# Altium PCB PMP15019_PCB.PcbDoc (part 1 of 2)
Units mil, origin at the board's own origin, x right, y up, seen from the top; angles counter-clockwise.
Board outline 3000 x 2000 mil, 6 copper layers (Top Layer, Signal Layer 1, Signal Layer 2, Signal Layer 3, Signal Layer 4, Bottom Layer), stack 61.6 mil thick; 82 components, 32 nets, 164 pads, 220 vias.
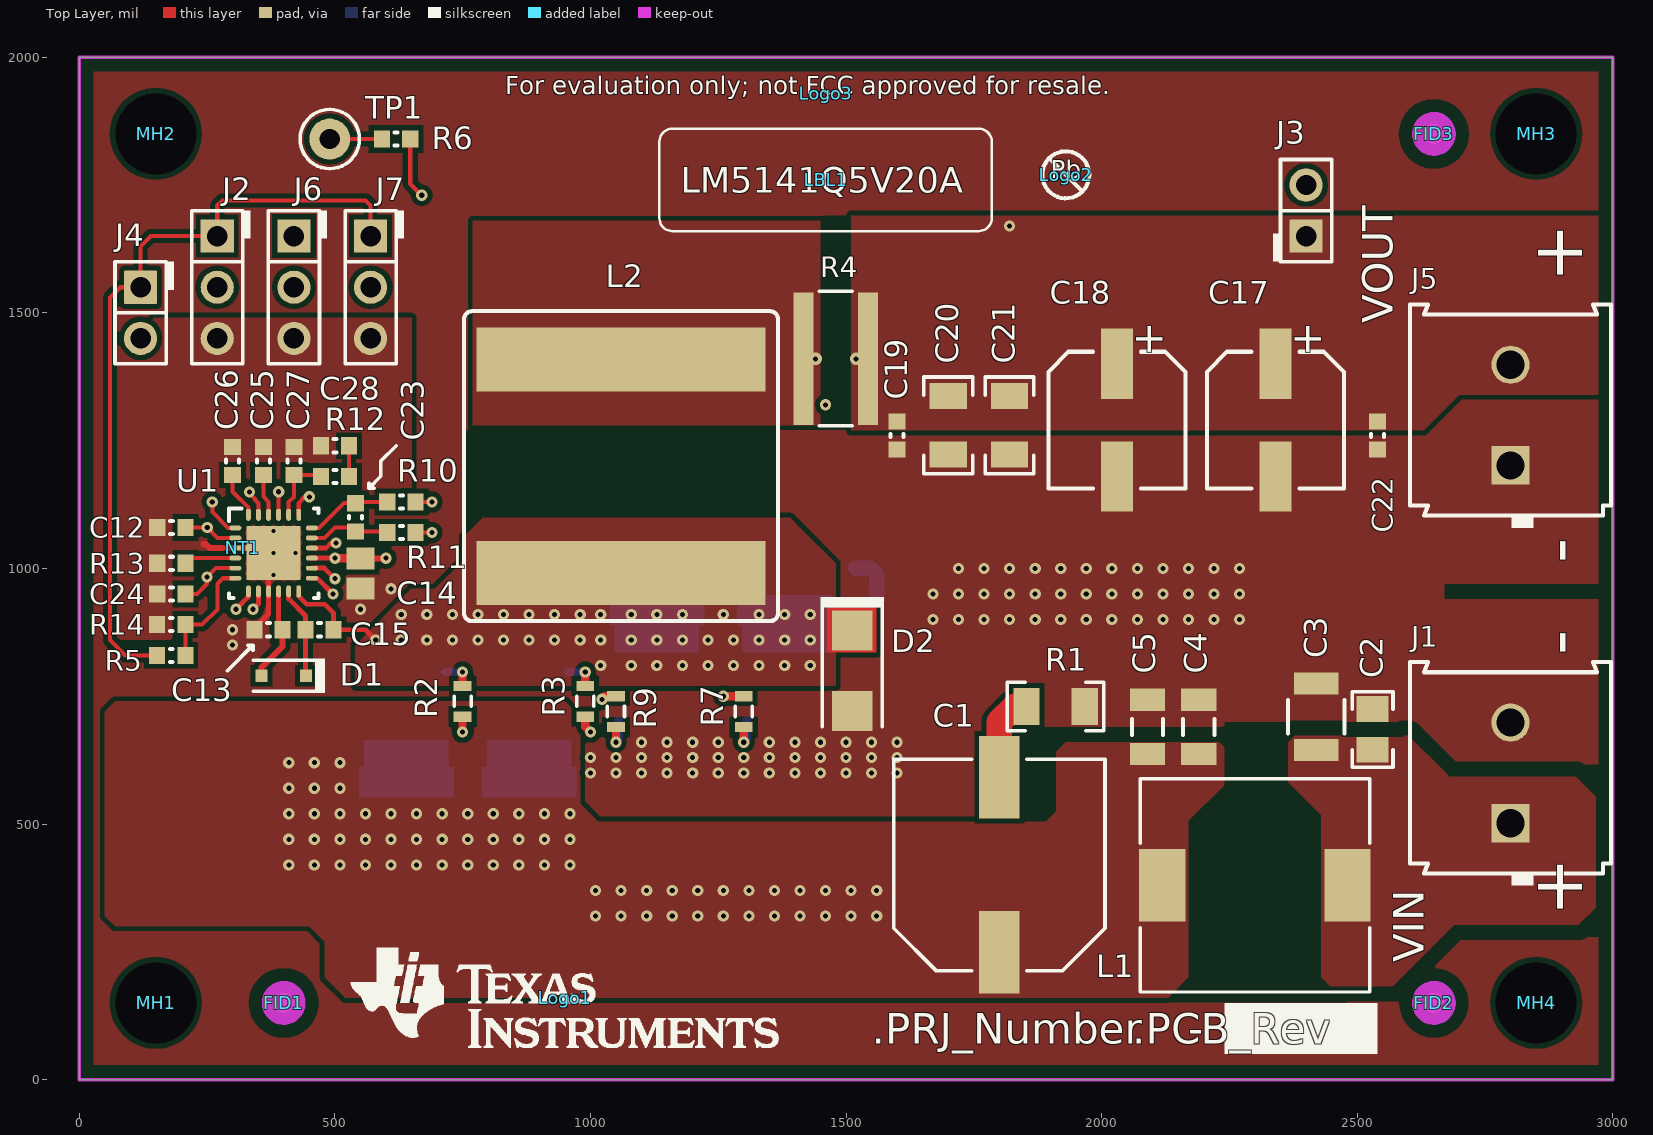
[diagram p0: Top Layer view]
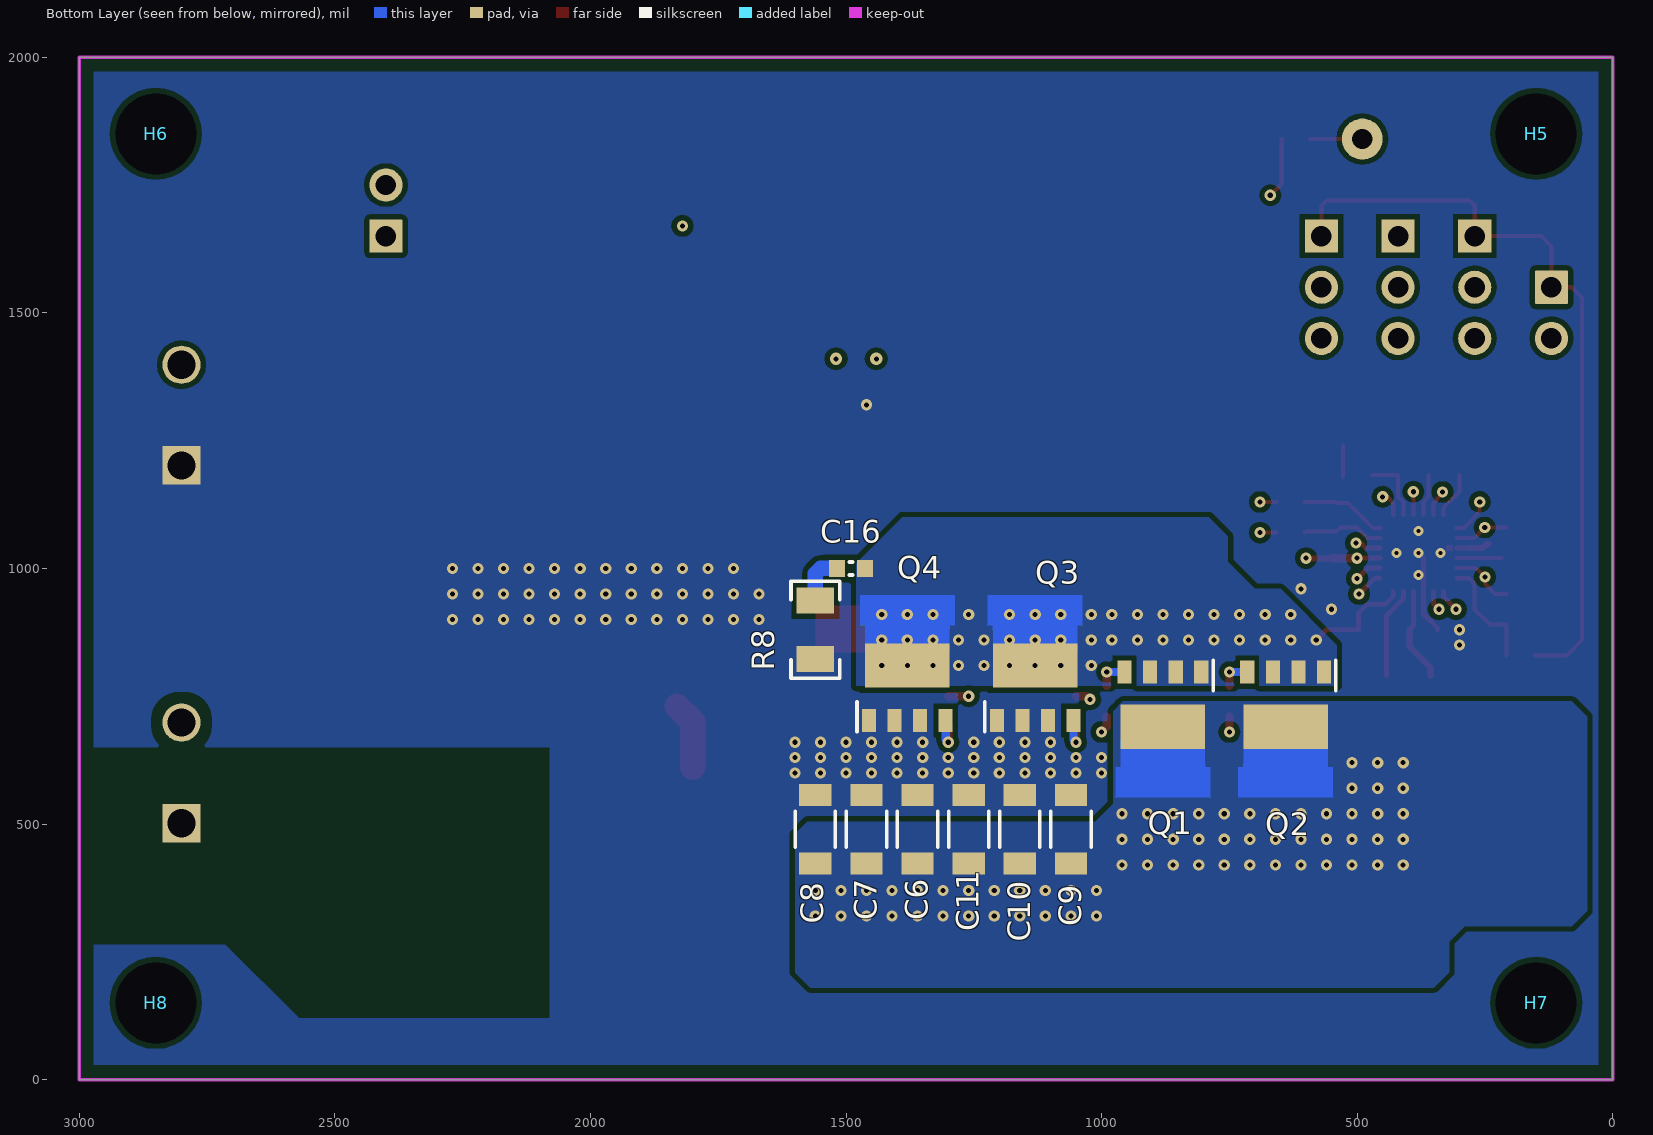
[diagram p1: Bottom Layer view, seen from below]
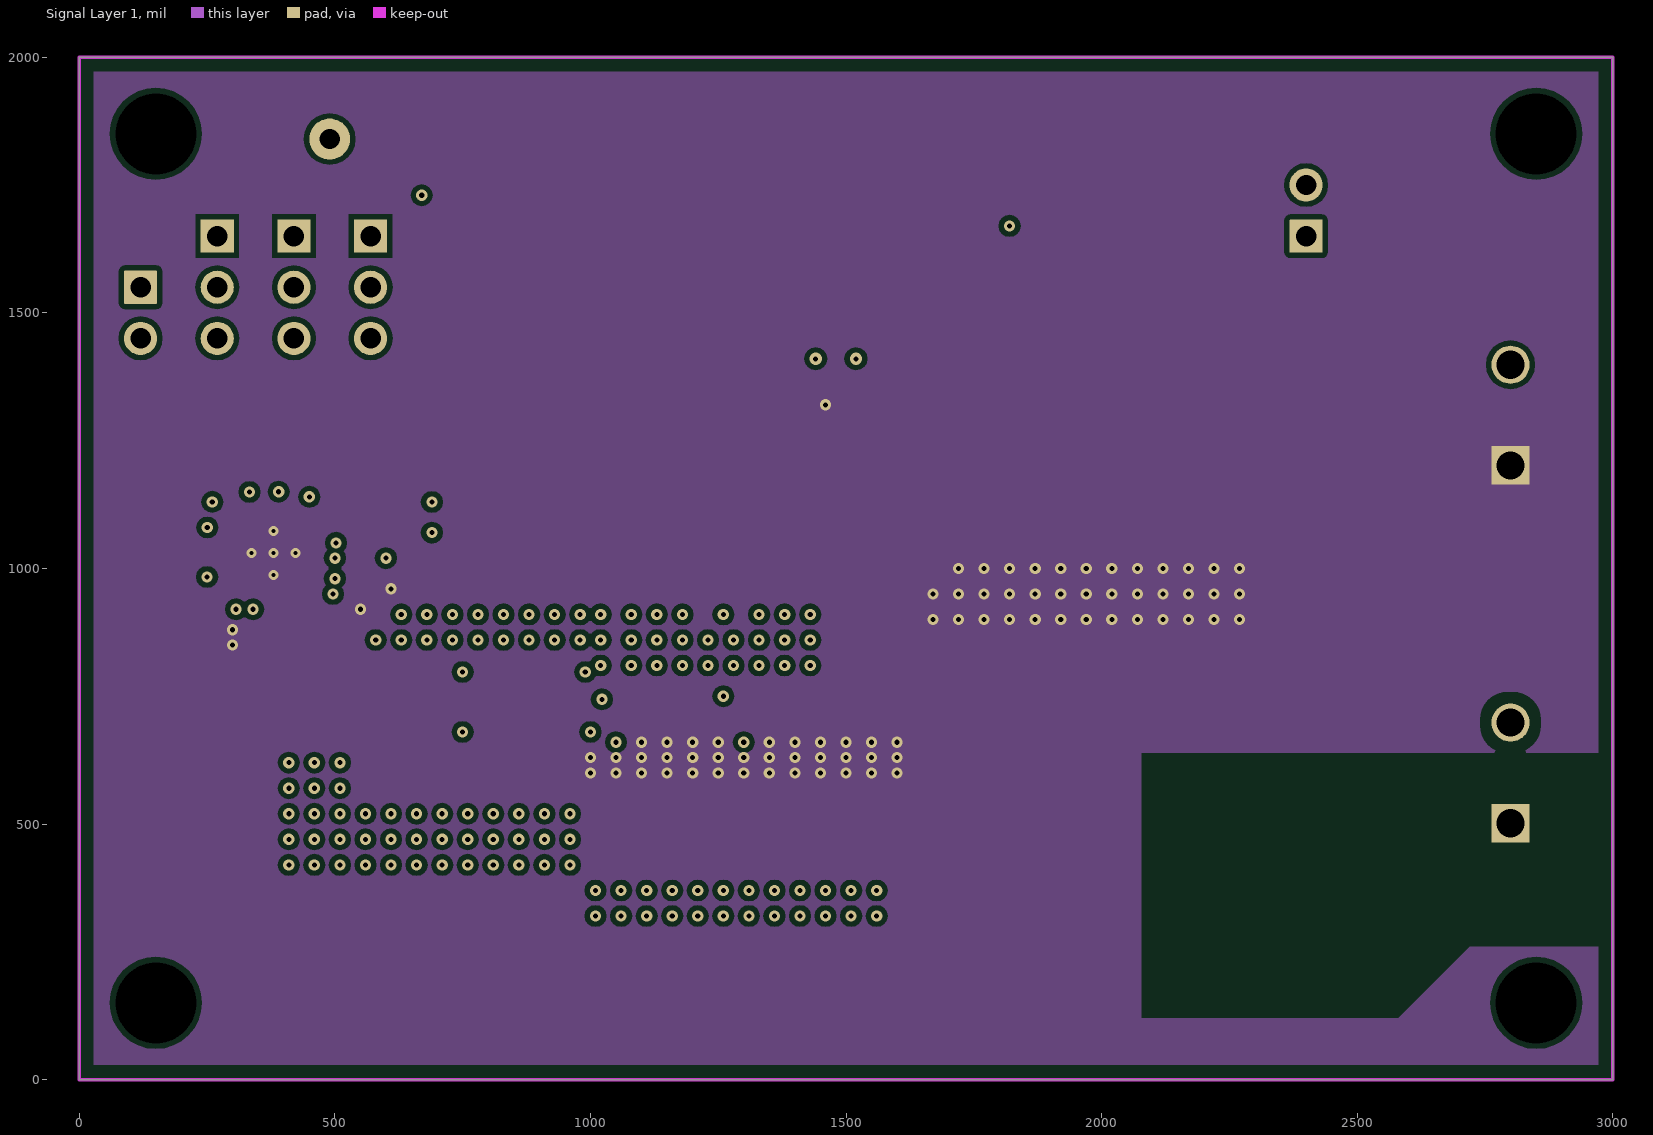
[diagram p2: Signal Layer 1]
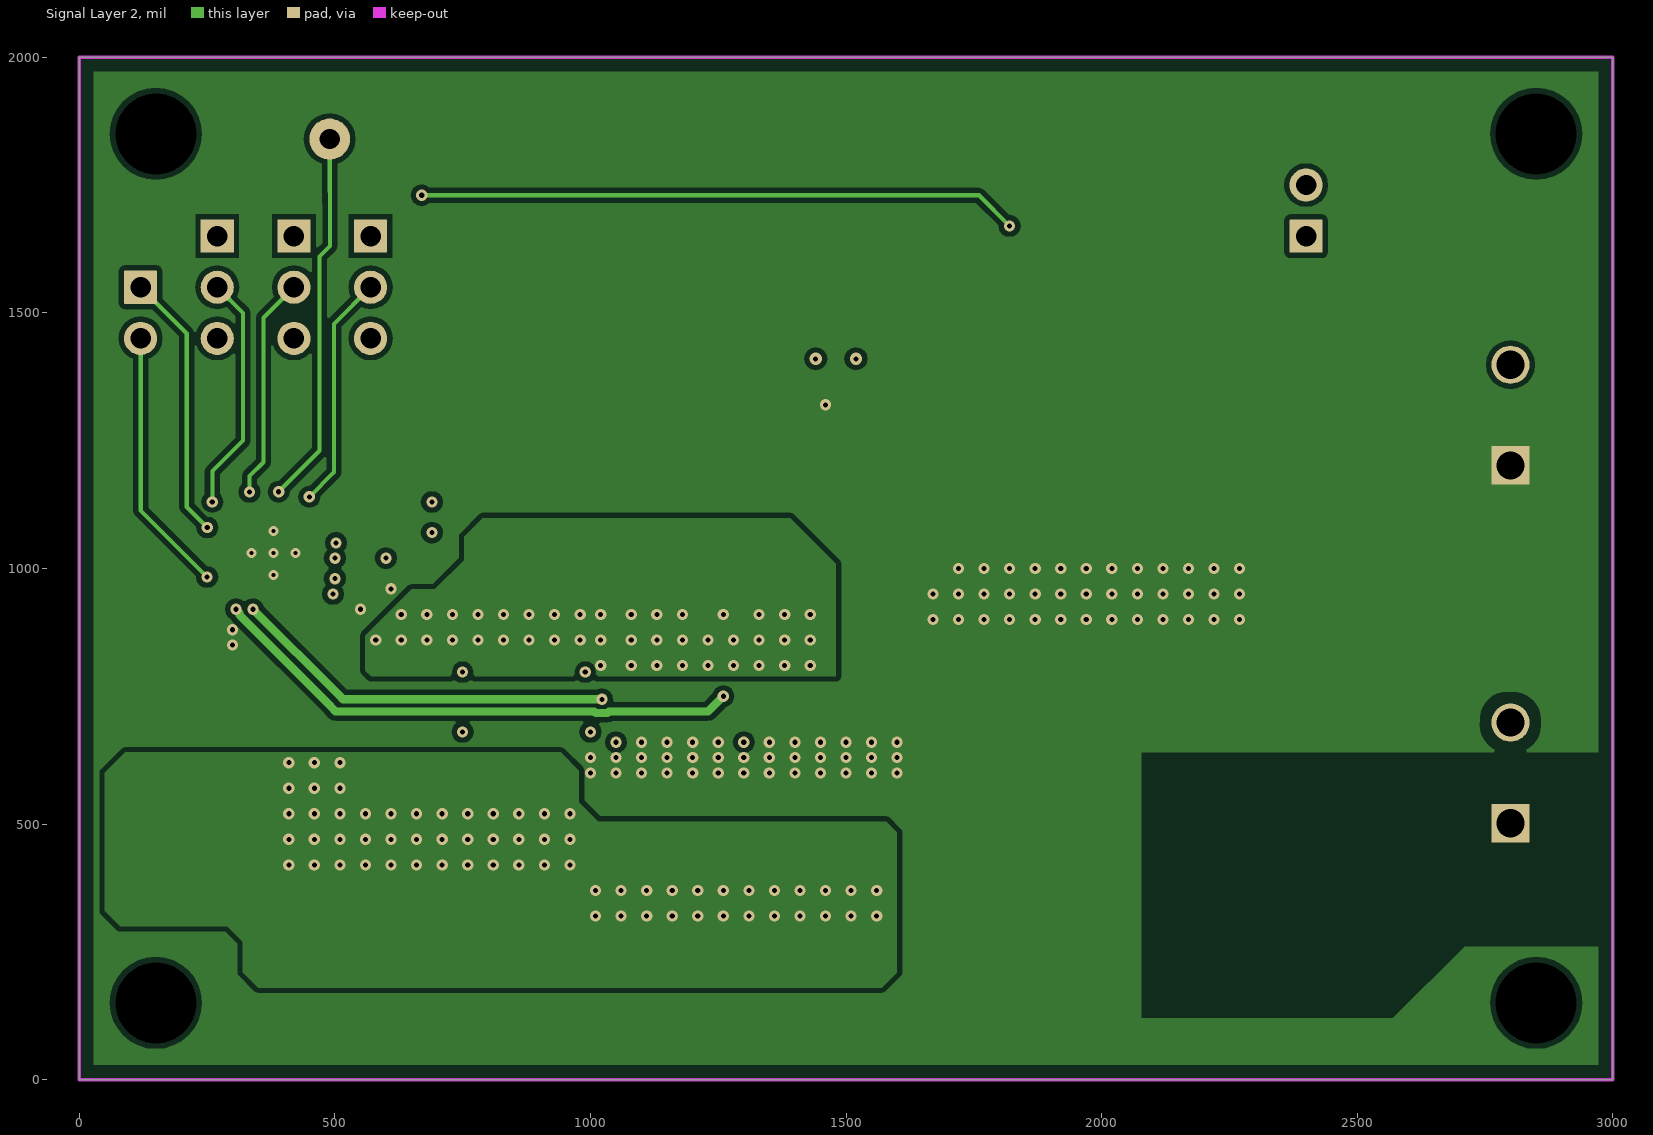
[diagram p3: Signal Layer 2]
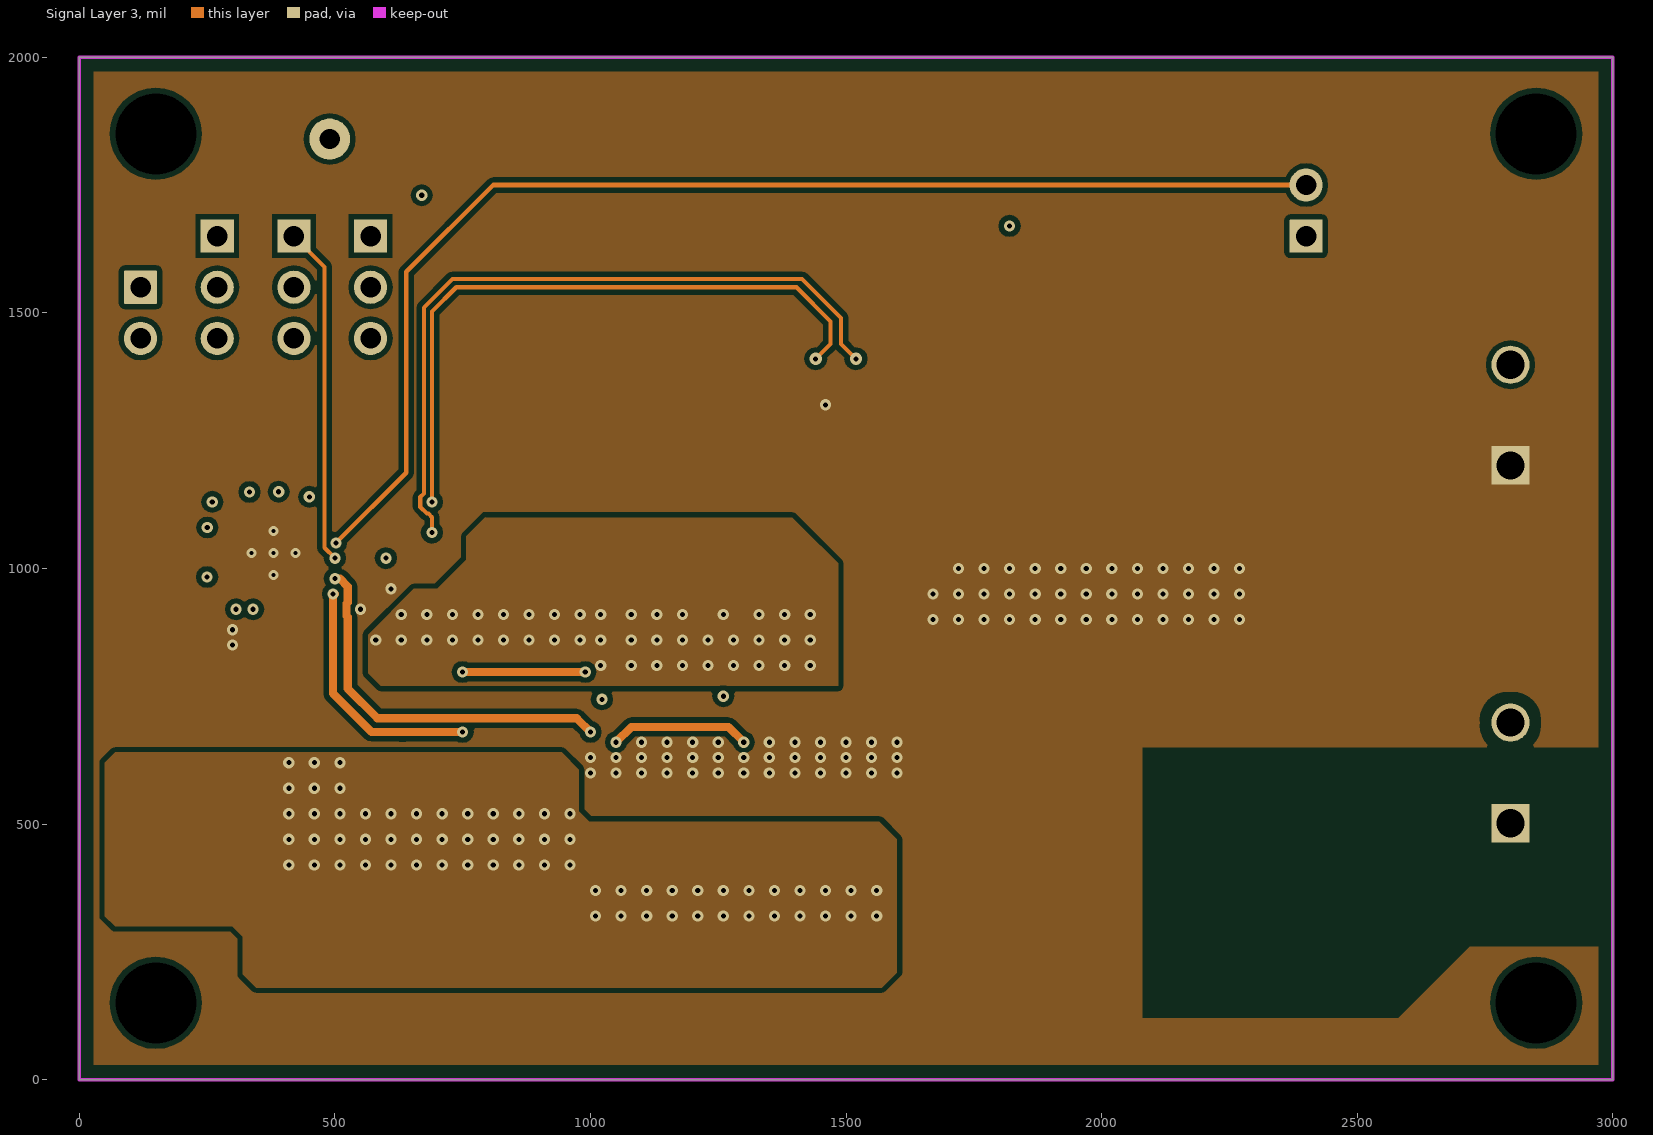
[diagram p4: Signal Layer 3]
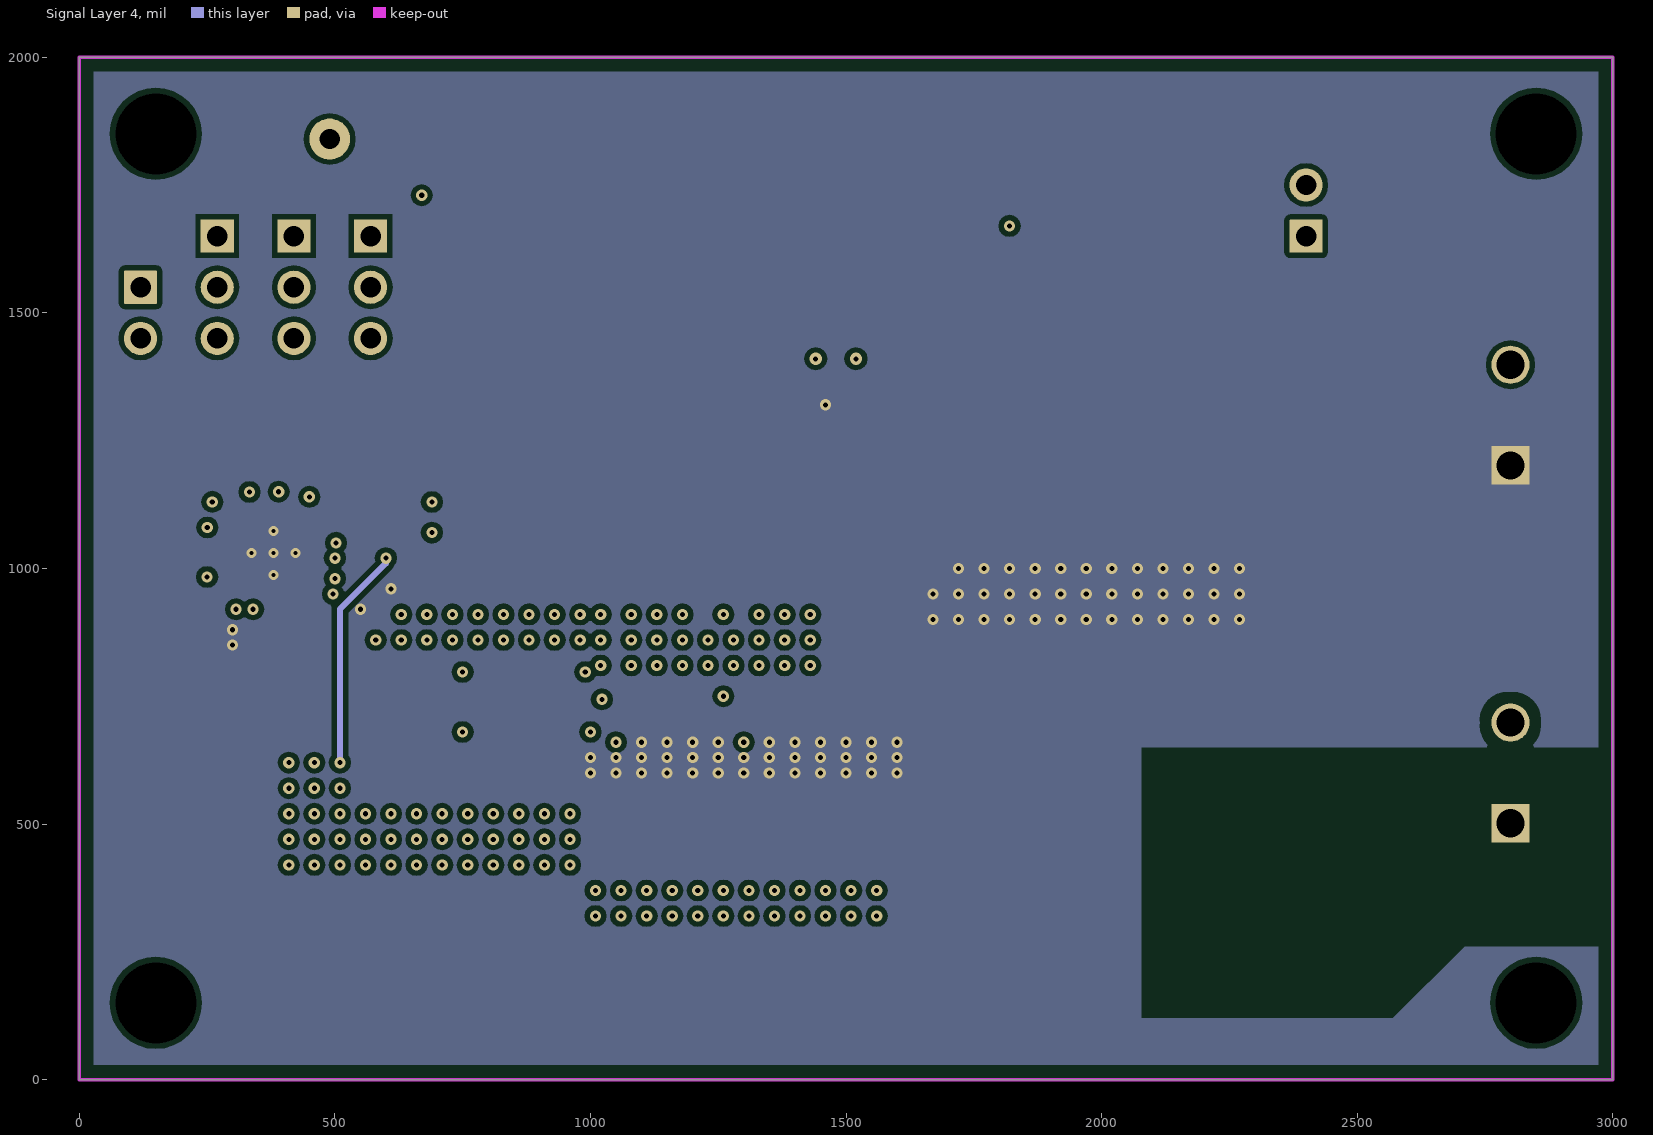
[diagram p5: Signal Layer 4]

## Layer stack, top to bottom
Top Solder: solder mask 0.4, Solder Resist, Dk 3.5
Top Layer: signal copper 4.2
Dielectric1: core 5, FR-4, Dk 4.8
Signal Layer 1: signal copper 2.8
Dielectric 3: prepreg 5, Dk 4.2
Signal Layer 2: signal copper 2.8
Dielectric 4: core 22, Dk 4.2
Signal Layer 3: signal copper 2.8
Dielectric 5: prepreg 5, Dk 4.2
Signal Layer 4: signal copper 2.8
Dielectric 2: core 5, Dk 4.2
Bottom Layer: signal copper 4.2
Bottom Solder: solder mask 0.4, Solder Resist, Dk 3.5

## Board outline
0,0 0,2000 3000,2000 3000,0

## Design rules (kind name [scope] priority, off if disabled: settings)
AcuteAngle [All] p1: minimum=4.50000000000000E+0001 checktracksonly=FALSE
AssemblyTestPointUsage [All] p1: valid=2
Clearance Clearance_Input [InNet('NetC2_1')] p1: gap=30
Clearance Clearance_Keepouts [((IsTrack Or IsArc) And Not InPoly) And IsFree and IsKeepOut vs ((IsTrack Or IsArc) And Not InPoly) And IsFree and IsKeepOut] p2: gap=0
Clearance Clearance_BoardEdge_MountingHoles [OnCopper and InComponentClass('Mounting Holes') vs IsKeepOut] p3: gap=40
Clearance Clearance_BoardEdge_Poly [OnCopper and InPoly vs IsKeepOut] p4: gap=25
Clearance Clearance_BoardEdge [OnCopper and Not InComponentClass('Logo') and not InComponentClass('FiducialMark') and not InRegion(1000,500,4000,800) and Not IsKeepout vs IsKeepOut] p5: gap=50
Clearance Clearance_Poly [InPolygon] p6: gap=10
Clearance [All] p7: gap=7.87
ComponentClearance ComponentClearance_NetTie [HasFootprint('RGE0024H') vs HasFootprint('Net-Tie_10mil')] p1: gap=0 collisioncheckmode=3 verticalgap=0 showdistances=FALSE
ComponentClearance ComponentClearance_MountingHoles_FiducialMarks [InComponentClass('Mounting Holes') vs InComponentClass('FiducialMark')] p2: gap=50 collisioncheckmode=3 verticalgap=10 showdistances=FALSE
ComponentClearance ComponentClearance_Shunt [InComponentClass('Header') vs InComponentClass('Shunt')] p3: gap=0 collisioncheckmode=3 verticalgap=0 showdistances=FALSE
ComponentClearance ComponentClearance_Logo [InComponentClass('Logo')] p4: gap=50 collisioncheckmode=3 verticalgap=10 showdistances=FALSE
ComponentClearance ComponentClearance_ScrewToNut [(HasFootprint('NY PMS 440 0025 PH')) vs (HasFootprint('Keystone_1902C'))] p5: gap=5 collisioncheckmode=3 verticalgap=10 showdistances=FALSE
ComponentClearance ComponentClearance_MountingHoles [InComponentClass('Mounting Holes')] p6: gap=250 collisioncheckmode=3 verticalgap=100000 showdistances=FALSE
ComponentClearance ComponentClearance_SmallPassives [HasFootprint('0201*') or HasFootprint('0402*') or HasFootprint('0508') or HasFootprint('0603*') or HasFootprint('0612') or HasFootprint('0805*') or HasFootprint('0815*') or HasFootprint('0830*') or HasFootprint('1206*') or HasFootprint('1210*') or HasFootprint('1808*') or HasFootprint('1812*') or HasFootprint('1825*') or HasFootprint('2010*') or HasFootprint('2220*') or HasFootprint('2225*') or HasFootprint('2512*') or HasFootprint('2728*') or HasFootprint('3518*') vs HasFootprint('0201*') or HasFootprint('0402*') or HasFootprint('0508') or HasFootprint('0603*') or HasFootprint('0612') or HasFootprint('0805*') or HasFootprint('0815*') or HasFootprint('0830*') or HasFootprint('1206*') or HasFootprint('1210*') or HasFootprint('1808*') or HasFootprint('1812*') or HasFootprint('1825*') or HasFootprint('2010*') or HasFootprint('2220*') or HasFootprint('2225*') or HasFootprint('2512*') or HasFootprint('2728*') or HasFootprint('3518*')] p7: gap=20 collisioncheckmode=3 verticalgap=10 showdistances=FALSE
ComponentClearance ComponentClearance_THtoSMT [IsThruComponent vs IsSMTComponent] p8: gap=40 collisioncheckmode=3 verticalgap=30 showdistances=FALSE
ComponentClearance ComponentClearance_THtoTH [IsThruComponent vs IsThruComponent] p9: gap=40 collisioncheckmode=3 verticalgap=30 showdistances=FALSE
ComponentClearance [All] p10: gap=40 collisioncheckmode=3 verticalgap=10 showdistances=FALSE
DiffPairsRouting [All] p1: maxlimit=100 minlimit=10 mostfreqgap=10 toplayer_minwidth=15 toplayer_maxwidth=15 toplayer_prefwidth=15 midlayer1_minwidth=15 midlayer1_maxwidth=15 midlayer1_prefwidth=15 midlayer2_minwidth=15 midlayer2_maxwidth=15 midlayer2_prefwidth=15 midlayer3_minwidth=15 midlayer3_maxwidth=15 midlayer3_prefwidth=15 midlayer4_minwidth=15 midlayer4_maxwidth=15 midlayer4_prefwidth=15 bottomlayer_minwidth=15 bottomlayer_maxwidth=15 bottomlayer_prefwidth=15 maxuncoupledlength=1000
FabricationTestPointUsage TestPointUsage [All] p1: valid=2 allowmultiple=FALSE
FabricationTestpoint Testpoint [All] p1: side=3 testpointundercomponent=TRUE minsize=40 maxsize=100 preferedsize=60 minholesize=0 maxholesize=40 preferedholesize=32 testpointgrid=1 allowsidetop=TRUE allowsidebottom=TRUE usegrid=TRUE gridtolerance=0.01
FanoutControl Fanout_LCC [IsLCC] p1: bgadir=Out bgaviamode=Centered fanoutstyle=Auto fanoutdirection=Alternating viagrid=1 // Fanout_LCC (Default Rule)
FanoutControl Fanout_BGA [IsBGA] p2: bgadir=Out bgaviamode=Centered fanoutstyle=Auto fanoutdirection=Alternating viagrid=1 // Fanout_BGA (Default Rule)
FanoutControl Fanout_Default [All] p4: bgadir=Out bgaviamode=Centered fanoutstyle=Auto fanoutdirection=Alternating viagrid=1 // Fanout_Default (Default Rule)
FanoutControl Fanout_Small [(CompPinCount < 5)] p5: bgadir=Out bgaviamode=Centered fanoutstyle=Auto fanoutdirection=OutThenIn viagrid=1 // Fanout_Small (Default Rule)
HoleSize [All] p1: absolutevalues=TRUE maxlimit=251 minlimit=7.87 maxpercent=80.000 minpercent=20.000
MinimumAnnularRing MinimumAnnularRing_ThermalPadVias [IsVia and InAnyComponent] p1: minimumring=5.91
MinimumAnnularRing [All] p2: minimumring=6
MinimumSolderMaskSliver MinimumSolderMaskSliver_Logo [InComponentClass('Logo') vs InComponentClass('Logo')] p1: minsoldermaskwidth=0.7
MinimumSolderMaskSliver [All] p2: minsoldermaskwidth=3.94
PlaneConnect [All] p1: planeconnectstyle=Relief reliefexpansion=10 reliefentries=4 reliefconductorwidth=10 reliefairgap=10
PolygonConnect [All] p1: connectstyle=Direct reliefconductorwidth=10 reliefentries=4 polygonreliefangle="90 Angle" airgapwidth=10
RoutingVias ThermalPadVias [IsVia and InAnyComponent] p1: holewidth=7.87 width=19.68 viastyle="Through Hole" minholewidth=7.87 minwidth=19.68 maxholewidth=12.99 maxwidth=23.62
RoutingVias [All] p2: holewidth=10 width=22 viastyle="Through Hole" minholewidth=7.87 minwidth=18 maxholewidth=40 maxwidth=65
SilkToBoardRegionClearance [Not ((IsComment or IsDesignator) And (Hide <> 'False')) and not InRegion(1000,500,4000,800)] p1:
SilkToSilkClearance SilkToSilkClearance_Pb-FreeLogo [(HasFootprint('Pb-Free_Overlay_Medium') OR HasFootprint('Pb-Free_Overlay_Small')) vs (HasFootprint('Pb-Free_Overlay_Medium') OR HasFootprint('Pb-Free_Overlay_Small'))] p1: silktosilkclearance=0
SilkToSilkClearance [All] p2: silktosilkclearance=4
SilkToSolderMaskClearance SilkToComonentPadClearance [IsPad and InAnycomponent] p1: minsilkscreentomaskgap=5 clearancetoexposedcopper=TRUE
SilkToSolderMaskClearance "Silk to Solder Mask Opening" [All] p2: minsilkscreentomaskgap=4 clearancetoexposedcopper=FALSE
SolderMaskExpansion [All] p1: expansion=1.97
Width [All] p1: maxlimit=100 minlimit=6 preferedwidth=10 checkconnectedcopper=TRUE
15 further rules are at their usual default settings.

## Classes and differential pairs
component class LM5141Q5V20A_BlankSheet: C1 C2 C3 C4 C5 C6 C7 C8 C9 C10 C11 C12 C13 C14 C15 C16 C17 C18 C19 C20 C21 C22 C23 C24 C25 C26 C27 C28 D1 D2 J1 J2 J3 J4 J5 J6 J7 L1 L2 NT1 Q1 Q2 Q3 Q4 R1 R2 R3 R4 R5 R6 R7 R8 R9 R10 R11 R12 R13 R14 TP1 U1 ZX1 ZX2 ZX3
component class Header: J2 J3 J4 J6 J7
component class Label: LBL1
component class AssemblyNote: ZX1 ZX2 ZX3 ZZ1 ZZ2 ZZ3 ZZ4
component class FiducialMark: FID1 FID2 FID3
component class LM5141Q5V20A_EVM_Hardware: FID1 FID2 FID3 H5 H6 H7 H8 LBL1 Logo1 Logo2 Logo3 MH1 MH2 MH3 MH4 ZZ1 ZZ2 ZZ3 ZZ4
component class Logo: Logo1

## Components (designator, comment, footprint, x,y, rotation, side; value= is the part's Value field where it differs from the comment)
C1 "EEE-FC1H470P" SM_RADIAL_G 1800,420 r90 top
C2 "C0805C104K1RACTU" 0805_HV 2530,685 r90 top
C3 "C3225X7R1H106M250AC" 1210_280 2420,710 r90 top
C4 "C3216X7R2A105M160AA" 1206L 2190,690 r90 top
C5 "C3216X7R2A105M160AA" 1206L 2090,690 r90 top
C6 "CL31B225KCHSNNE" 1206_190 1360,490 r90 bottom
C7 "CL31B225KCHSNNE" 1206_190 1460,490 r90 bottom
C8 "CL31B225KCHSNNE" 1206_190 1560,490 r90 bottom
C9 "CL31B225KCHSNNE" 1206_190 1060,490 r90 bottom
C10 "CL31B225KCHSNNE" 1206_190 1160,490 r90 bottom
C11 "CL31B225KCHSNNE" 1206_190 1260,490 r90 bottom
C12 "C0603C104K5RACTU" 0603L 180.16,1080 r0 top
C13 "GRM188R61C475KAAJ" 0603L 370.16,880 r0 top
C14 "GRM21BR72A474KA73L" 0805L 550.16,990 r90 top
C15 "C0603C104K5RACTU" 0603L 470.16,880 r0 top
C16 "GRM1885C2A102JA01D" 0603L 1490,1000 r0 bottom
C17 "875105344009" WCAP-PSLP_630x580 2340,1290 r270 top
C18 "875105344009" WCAP-PSLP_630x580 2030,1290 r270 top
C19 "C0603C104K5RACTU" 0603L 1600,1260 r270 top
C20 "C3216X5R1C476M160AB" 1206 1700,1280 r270 top
C21 "C3216X5R1C476M160AB" 1206 1820,1280 r270 top
C22 "C0603C104K5RACTU" 0603L 2540,1260 r270 top
C23 "06035A330JAT2A" 0603L 540.16,1100 r90 top
C24 "CGA3E2X7R2A103K080AA" 0603L 180.16,950 r180 top
C25 "GRM188R71E683KA01D" 0603L 360.16,1210 r90 top
C26 "CGA3E2X7R2A103K080AA" 0603L 300.16,1210 r90 top
C27 "CGA3E2C0G1H220J080AA" 0603L 420.16,1210 r90 top
C28 "CGA3E2X7R2A103K080AA" 0603L 500.16,1240 r180 top
D1 "PMEG6010CEJ,115" SOD-323F 400.16,790 r180 top
D2 "SS25S-E3/5AT" SMA 1512.36,800 r270 top
FID1 "Fiducial" Fiducial10-20 400,150 r0 top
FID2 "Fiducial" Fiducial10-20 2650,150 r0 top
FID3 "Fiducial" Fiducial10-20 2650,1850 r0 top
H5 "1902C" Keystone_1902C 150,1850 r180 bottom locked
H6 "1902C" Keystone_1902C 2850,1850 r180 bottom locked
H7 "1902C" Keystone_1902C 150,150 r180 bottom locked
H8 "1902C" Keystone_1902C 2850,150 r180 bottom locked
J1 "282856-2" TE_282856-2 2800,600 r90 top
J2 "TSW-103-07-G-S" TSW-103-07-G-S 270,1550 r270 top
J3 "TSW-102-07-G-S" TSW-102-07-G-S 2400,1700 r90 top
J4 "TSW-102-07-G-S" TSW-102-07-G-S 120,1500 r270 top
J5 "282856-2" TE_282856-2 2800,1300 r90 top
J6 "TSW-103-07-G-S" TSW-103-07-G-S 420,1550 r270 top
J7 "TSW-103-07-G-S" TSW-103-07-G-S 570,1550 r270 top
L1 "7443330220" WE-HCC_1090 2300,380 r180 top
L2 "XAL1580-202MEB" XAL1580 1060,1200 r90 top
LBL1 "LM5141Q5V20A" Label_650x200 1460,1760 r0 top
Logo1 "Texas Instruments" TI_Stacked_Overlay_Small 950,160 r0 top
Logo2 "Pb-Free Symbol" Pb-Free_Overlay_Small 1930,1770 r0 top
Logo3 "FCC disclaimer" FCC_disclaimer 1460,1930 r0 top
MH1 "MTG_NoPads" MTG_159mil 150,150 r0 top
MH2 "MTG_NoPads" MTG_159mil 150,1850 r0 top
MH3 "MTG_NoPads" MTG_159mil 2850,1850 r0 top
MH4 "MTG_NoPads" MTG_159mil 2850,150 r0 top
NT1 "Net-Tie" Net-Tie_10mil 320.16,1040 r0 top net-tie
Q1 "BUK9Y21-40E,115" LFPAK56 880,690 r0 bottom
Q2 "BUK9Y21-40E,115" LFPAK56 640,690 r0 bottom
Q3 "BUK9Y21-40E,115" LFPAK56 1130,810 r180 bottom
Q4 "BUK9Y21-40E,115" LFPAK56 1380,810 r180 bottom
R1 "CRCW12061R00JNEA" 1206 1910,730 r180 top
R2 "CRCW060310R0FKEAHP" 0603S 750,740 r90 top
R3 "CRCW06030000Z0EA" 0603S 990,740 r270 top
R4 "0.003" 2512_WIDE 1480,1410 r0 top
R5 "CRCW06030000Z0EA" 0603L 180,830 r0 top
R6 "CRCW060310K0FKEA" 0603L 620,1840 r180 top
R7 "CRCW060310R0FKEAHP" 0603S 1300,720 r270 top
R8 "CRM1206-JW-1R0ELF" 1206 1560,880 r90 bottom
R9 "CRCW060310R0FKEAHP" 0603S 1050,720 r90 top
R10 "CRCW060349R9FKEA" 0603L 630.16,1130 r0 top
R11 "CRCW06030000Z0EA" 0603L 630.16,1070 r0 top
R12 "CRCW06035K49FKEA" 0603L 500.16,1180 r180 top
R13 "CRCW06030000Z0EA" 0603L 180.16,1010 r0 top
R14 "CRCW06030000Z0EA" 0603L 180,890 r180 top
TP1 "5002" Keystone5002 490.02,1840 r270 top
U1 "LM5141QRGERQ1" RGE0024H 380.16,1030 r0 top
ZX1 "VIN = 6 - 42VDC" AssemblyNote 180,4690 r0 top
ZX2 "Fsw =460KHz" AssemblyNote 180,4554 r0 top
ZX3 "VOUT = 5.0VDC @ 20A" AssemblyNote 180,4418 r0 top
ZZ1 "This Assembly Note is for PCB labels only" AssemblyNoteLabel 185,3938 r0 top
ZZ2 "These assemblies are ESD sensitive, ESD precautions shall be observed." AssemblyNote 185,3829.11 r0 top
ZZ3 "These assemblies must be clean and free from flux and all contaminants. Use of no clean flux is not acceptable." AssemblyNote 185,3740.56 r0 top
ZZ4 "These assemblies must comply with workmanship standards IPC-A-610 Class 2, unless otherwise specified." AssemblyNote 185,3652 r0 top

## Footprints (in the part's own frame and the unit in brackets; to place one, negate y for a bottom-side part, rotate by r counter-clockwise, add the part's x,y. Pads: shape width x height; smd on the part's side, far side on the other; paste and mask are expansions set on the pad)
0603L [mm] "0603 from SM-752 data"
  rect 0.8x0.85 smd: 1(-0.7,0) 2(0.7,0)
  silkscreen extent -0.07,-0.33 0.07,0.33, body extent -0.87,-0.47 0.87,0.47, height 1
0603S [mil]
  rect 20x35 smd: 1(-30,0) 2(30,0)
  silkscreen extent -10,-17 10,17, body extent -34,-19 34,19, height 39
0805_HV [mil] "0805 with 30mil clearance between pads"
  rect 50x63 smd: 1(-40,0) 2(40,0)
  silkscreen extent -74,-40 74,40, body extent -43,-29 43,29, height 57
0805L [mm] "0805 from SM-752 data"
  rect 1.1x1.4 smd: 1(-0.75,0) 2(0.75,0)
  body extent -1.1,-0.72 1.1,0.72, height 1.45
1206 [mm] "1206 from SM-752 data"
  rect 1.3x1.85 smd: 1(-1.45,0) 2(1.45,0)
  silkscreen extent -2.4,-1.21 2.4,1.21, body extent -1.7,-0.9 1.7,0.9, height 1.35
1206_190 [mm] "1206_190"
  rect 1.1x1.6 smd: 1(-1.7,0) 2(1.7,0)
  silkscreen extent -0.9,-1 0.9,1, body extent -1.75,-0.95 1.75,0.95, height 1.9
1206L [mm] "1206 from SM-752 data"
  rect 1.1x1.75 smd: 1(-1.35,0) 2(1.35,0)
  silkscreen extent -0.4,-0.77 0.4,0.77, body extent -1.7,-0.9 1.7,0.9, height 1.35
1210_280 [mm] "SMD, 2-Leads, Body 3.6x2.8mm, Height 2.8mm"
  rect 1.1x2.2 smd: 1(-1.65,0) 2(1.65,0)
  silkscreen extent -0.84,-1.4 0.84,1.4, body extent -1.8,-1.4 1.8,1.4, height 2.8
2512_WIDE [mm] "Ohmite recommended land pattern"
  rect 1x6.6 smd: 1(-1.6,0) 2(1.6,0)
  silkscreen extent -0.82,-3.32 0.82,3.35, body extent -1.65,-3.25 1.65,3.25, height 0.7
AssemblyNote [mil] "Assembly Note"
AssemblyNoteLabel [mil] "Assembly Note for PCB Labels"
FCC_disclaimer [mil]
Fiducial10-20 [mm]
  round 1 smd mask+0.5: 1(0,0)
  Top Layer keep-out circle w1.178: c0,0 r0.5
Keystone5002 [mil] "For Keystone 500x miniature loop terminals"
  round 80 hole 40: 1(0,0)
  silkscreen extent -58,-58 58,58, body extent -49,-49 49,49, height 182
Keystone_1902C [mil] "Hex Standoff, 4-40 threaded, nylon"
  body extent -145,-126 146,126, height 501
Label_650x200 [mil] "Thermal Transfer Label"
  silkscreen extent -325,-100 325,100, body extent -325,-100 325,100, height 1
LFPAK56 [mm] "NXP Semiconductor"
  rect 0.7x1.15 smd paste-0.05: 1(-1.905,-2.725) 2(-0.635,-2.725) 3(0.635,-2.725) 4(1.905,-2.725)
  rect 4.2x2.2 smd paste-1.52: 5(0,0)
  Top Layer region: -2.1,2 2.1,2 2.1,0.65 -2.1,0.65
  Top Layer region: -2.1,1.8 -2.1,2 -2.35,2 -2.35,3.5 2.35,3.5 2.35,2 2.1,2 2.1,1.8
  silkscreen extent -2.5,-3.3 -2.5,-1.8, body extent -2.43,-3.14 2.47,3.29, height 1.18
MTG_159mil [mil] "159mil Non Plated Hole"
  round 150 hole 159 unplated: 1(0,0)
Net-Tie_10mil [mil] "10mil net tie, no solder mask opening, no solder paste"
  rect 10x10 smd paste-5 mask-5: 1(-10,0) 2(10,0)
  Top Layer region: -6,5 6,5 6,-5 -6,-5
Pb-Free_Overlay_Small [mil]
  silkscreen extent -46,-46 46,46
RGE0024H [mm] "QFN, 24-Leads, Body 4x4mm, Pitch 0.5mm, Thermal Pad 2.7x2.7mm, TI Recommended"
  oval 0.6x0.24 smd: 1(-1.9,1.25) 2(-1.9,0.75) 3(-1.9,0.25) 4(-1.9,-0.25) 5(-1.9,-0.75) 6(-1.9,-1.25) 13(1.9,-1.25) 14(1.9,-0.75) 15(1.9,-0.25) 16(1.9,0.25) 17(1.9,0.75) 18(1.9,1.25)
  oval 0.24x0.6 smd: 7(-1.25,-1.9) 8(-0.75,-1.9) 9(-0.25,-1.9) 10(0.25,-1.9) 11(0.75,-1.9) 12(1.25,-1.9) 19(1.25,1.9) 20(0.75,1.9) 21(0.25,1.9) 22(-0.25,1.9) 23(-0.75,1.9) 24(-1.25,1.9)
  rect 2.7x2.7 smd paste-1.35: 25(0,0)
  silkscreen extent -2.22,-2.22 2.22,2.22, body extent -2.07,-2.07 2.07,2.07, height 1.01
SM_RADIAL_G [mm] "10 x 10.2mm:  Panasonic G"
  rect 4.1x2 smd: 1(-4.35,0) 2(4.35,0)
  silkscreen extent -5.25,-5.25 5.25,5.25, body extent -5.25,-5.25 5.25,5.25, height 10.5
SMA [mm] "Molded Diode, 2-Leads, Body 4.3x2.6mm, IPC Medium Density, based on OnSemi component dimensions and land pattern"
  rect 2x2 smd: 1(-2,0) 2(2,0)
  silkscreen extent -3.66,-1.57 2.79,1.57, body extent -2.6,-1.3 2.6,1.3, height 2.42
SOD-323F [mm] "NXP recommended land pattern"
  rect 0.6x0.6 smd paste-0.05: 1(-1.1,0) 2(1.1,0)
  silkscreen extent -2.06,-0.86 1.53,0.86, body extent -1.35,-0.67 1.35,0.68, height 0.79
TE_282856-2 [mm] "TH, 2-Leads, Body 10x10mm, Pitch 5mm"
  rect 1.9x1.9 hole 1.4: 1(-2.5,0)
  round 1.9 hole 1.4: 2(2.5,0)
  silkscreen extent -5.61,-5 5.5,5, body extent -5,-5 5.5,5, height 19
TI_Stacked_Overlay_Small [mil]
  silkscreen extent -418,-98 418,98
TSW-102-07-G-S [mm] "Samtec 100mil, 1x2, 230 mil above insulator"
  rrect6% 1.65x1.65 hole 1.016: 1(-1.27,0)
  round 1.65 hole 1.016: 2(1.27,0)
  silkscreen extent -2.54,-1.27 2.54,1.65, body extent -2.54,-1.27 2.54,1.27, height 8.38
TSW-103-07-G-S [mm] "Samtec 100mil, 1x3, 230 mil above insulator"
  rect 1.65x1.65 hole 1.016: 1(-2.54,0)
  round 1.65 hole 1.016: 2(0,0) 3(2.54,0)
  silkscreen extent -3.81,-1.27 3.81,1.65, body extent -3.81,-1.27 3.81,1.27, height 8.38
WCAP-PSLP_630x580 [mm] "SMD, 2-Leads, Dia 6.3mm"
  rect 3.5x1.6 smd: 1(-2.8,0) 2(2.8,0)
  silkscreen extent -3.4,-3.4 3.4,3.4, body extent -3.4,-3.4 3.4,3.4, height 5.81
WE-HCC_1090 [mm] "WERTH"
  rect 2.3x3.6 smd: 1(-4.6,0) 2(4.6,0)
  silkscreen extent -5.7,-5.3 5.7,5.3, body extent -5.12,-5 5.13,5, height 9.87
XAL1580 [mm] "COILCRAFT"
  rect 3.18x14.36 smd: 1(-5.3,0) 2(5.3,0)
  silkscreen extent -7.7,-7.8 7.7,7.8, body extent -7.7,-7.8 7.7,7.8, height 8

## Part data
C1: "CAP, AL, 47 µF, 50 V, +/- 20%, 0.3 ohm, SMD"
C2: "CAP, CERM, 0.1 µF, 100 V, +/- 10%, X7R, 0805"
C3: "CAP, CERM, 10 µF, 50 V, +/- 20%, X7R, 1210"
C4 C5: "CAP, CERM, 1 µF, 100 V, +/- 20%, X7R, 1206"
C6 C7 C8 C9 C10 C11: "CAP, CERM, 2.2 µF, 100 V, +/- 10%, X7R, 1206_190"
C12 C15 C19 C22: "CAP, CERM, 0.1 µF, 50 V, +/- 10%, X7R, 0603"
C13: "CAP, CERM, 4.7 µF, 16 V, +/- 10%, X5R, 0603"
C14: "CAP, CERM, 0.47 µF, 100 V, +/- 10%, X7R, 0805"
C16: "CAP, CERM, 1000 pF, 100 V, +/- 5%, C0G/NP0, 0603"
C17 C18: "CAP, Aluminum Polymer, 82 µF, 16 V, +/- 20%, 0.03 ohm, D6.3xL5.8mm SMD"
C20 C21: "CAP, CERM, 47 µF, 16 V, +/- 15%, X5R, 1206"
C23: "CAP, CERM, 33 pF, 50 V, +/- 5%, C0G/NP0, 0603"
C24 C26 C28: "CAP, CERM, 0.01 µF, 100 V, +/- 10%, X7R, AEC-Q200 Grade 1, 0603"
C25: "CAP, CERM, 0.068 µF, 25 V, +/- 10%, X7R, 0603"
C27: "CAP, CERM, 22 pF, 50 V, +/- 5%, C0G/NP0, AEC-Q200 Grade 1, 0603"
D1: "Diode, Schottky, 60 V, 1 A, SOD-323F"
D2: "Diode, Schottky, 50 V, 2 A, AEC-Q101, SMA"
FID1 FID2 FID3: "Fiducial mark.  There is nothing to buy or mount."
H5 H6 H7 H8: "Standoff, Hex, 0.5\"L #4-40 Nylon"
J1 J5: "Therminal Block, 5 mm, 2-pole, Tin, TH"
J2 J6 J7: "Header, 100mil, 3x1, Gold, TH"
J3 J4: "Header, 100mil, 2x1, Gold, TH"
L1: "Inductor, Shielded Drum Core, Ferrite, 2.2 µH, 16.5 A, 0.0037 ohm, SMD"
L2: "Inductor, Shielded, Composite, 2 µH, 39.9 A, 0.001909 ohm, SMD"
LBL1: library part THT-14-423-10, "Thermal Transfer Printable Labels, 0.650\" W x 0.200\" H - 10,000 per roll"
Logo1: library part TI_Logo, "Texas Instrument Corporate Signature"
Logo2: library part Pb-Free
Logo3: library part FCC_disclaimer, "FCC_disclaimer"
MH1 MH2 MH3 MH4: library part "Mounting Hole (non-standard) No Pad", "PCB Mounting Hole, No Pad"
NT1: "Single point connection between nets."
Q1 Q2 Q3 Q4: "MOSFET, N-CH, 40 V, 33 A, AEC-Q101, SOT669"
R1: "RES, 1.0, 5%, 0.25 W, 1206"
R2 R7 R9: "RES, 10.0, 1%, 0.25 W, 0603"
R3 R5 R11 R13 R14: "RES, 0, 5%, 0.1 W, 0603"
R4: library part KRL6432E-M-R003-F-T1, "RES SMD 0.003 OHM 3W 2512 WIDE"
R6: "RES, 10.0 k, 1%, 0.1 W, 0603"
R8: "RES, 1.0, 5%, 0.5 W, 1206"
R10: "RES, 49.9, 1%, 0.1 W, 0603"
R12: "RES, 5.49 k, 1%, 0.1 W, 0603"
TP1: "Test Point, Miniature, White, TH"
U1: "Wide Input Range Buck Controller, RGE0024H"
ZX1 ZX2 ZX3: library part AssemblyNote, "This Assembly Note will show in the PcbDoc and associated outputs"
ZZ1: library part AssemblyNoteLabel
ZZ2 ZZ3 ZZ4: library part AssemblyNote

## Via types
v1: diameter 22, hole 10, Top Layer to Bottom Layer, tented both sides, 199 vias
v2: diameter 22, hole 10, Top Layer to Bottom Layer, 14 vias
v3: diameter 19.68, hole 7.87, Top Layer to Bottom Layer, 5 vias
v4: diameter 24, hole 10, Top Layer to Bottom Layer, tented both sides, 2 vias

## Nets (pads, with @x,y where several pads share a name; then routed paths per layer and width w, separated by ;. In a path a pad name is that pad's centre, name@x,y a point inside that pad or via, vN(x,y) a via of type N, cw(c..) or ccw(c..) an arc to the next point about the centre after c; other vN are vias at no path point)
AGND: C12.1 C24.2 C25.2 C26.2 C27.2 C28.2 J2.3 J6.3 J7.3 NT1.1 R13.1 R14.2 U1.3 | length 65.5
  Top Layer w10: 280.32,1039.84 U1.3@305.35,1039.84
  Top Layer w12: 242.89,1047.27 247.61,1047.27 254.88,1040 280.16,1040 280.32,1039.84
NetC1_2: C1.2 R1.2 | length 131.2
  Top Layer w50: C1.2@1800,611.26 1800,700 R1.2@1830,730
NetC2_1: C2.1 C3.1 J1.1 L1.1
NetC15_1: C15.1 D1.1 U1.11 | length 179.2
  Top Layer w9.5: U1.11@409.69,955.2 409.69,940.47 442.6,907.56 C15.1@442.6,880 442.6,790.87 D1.1@443.46,790
NetC15_2: C15.2 C16.1 D2.1 L2.1 Q1.1 Q1.2 Q1.3 Q2.1 Q2.2 Q2.3 Q3.5 Q4.5 U1.12 | length 214.8
  Top Layer w9.5: U1.12@429.37,955.2 429.37,945.36 444.73,930 480.16,930 497.72,912.44 C15.2@497.72,880 560,880 v1(580,860)
  other v1: 1020,810 1080,810 1130,810 1180,810 1230,810 1280,810 1330,810 1380,810 1430,810 630,860 680,860 730,860 780,860 830,860 880,860 930,860 980,860 1020,860 1080,860 1130,860 1180,860 1230,860 1280,860 1330,860 1380,860 1430,860 630,910 680,910 730,910 780,910 830,910 880,910 930,910 980,910 1020,910 1080,910 1130,910 1180,910 1260,910 1330,910 1380,910 1430,910
NetC16_2: C16.2 R8.2 | length 99.5
  Bottom Layer w30: C16.2@1517.56,1000 1550,1000 1560,990 R8.2@1560,937.09
NetC23_1: C23.1 R11.1 U1.17 | length 160.4
  Top Layer w8: U1.17@454.96,1059.53 479.69,1059.53 500.32,1080.16 532.44,1080.16 C23.1@540.16,1072.44 600.16,1072.44 R11.1@602.6,1070
NetC23_2: C23.2 R10.1 U1.18 | length 168.7
  Top Layer w8: U1.18@454.96,1079.21 469.37,1079.21 517.72,1127.56 C23.2@540.16,1127.56 542.6,1130 R10.1@602.6,1130
NetC24_1: C24.1 J4.2 U1.5 | length 647
  Top Layer w8: C24.1@207.72,950 230.16,950 250.16,970 v2(250.16,983.27) 267.36,1000.47 U1.5@305.35,1000.47
  Signal Layer 2 w8: J4.2@120.32,1450.16 120.32,1113.11 v2(250.16,983.27)
NetC25_1: C25.1 U1.22 | length 81.8
  Top Layer w8: C25.1@360.16,1182.44 360.16,1140.32 370.32,1130.16 U1.22@370.32,1104.8
NetC26_1: C26.1 U1.24 | length 90.4
  Top Layer w8: C26.1@300.16,1182.44 300.16,1150 330.94,1119.21 U1.24@330.94,1104.8
NetC27_1: C27.1 R12.2 U1.20 | length 132
  Top Layer w8: U1.20@409.69,1104.8 409.69,1129.53 420.16,1140 C27.1@420.16,1182.44 R12.2@470.16,1182.44
NetC28_1: C28.1 R12.1 | length 60
  Top Layer w8: R12.1@527.72,1180 C28.1@527.72,1240
NetJ2_2: J2.2 U1.1 | length 543.4
  Top Layer w8: v2(260.32,1130.16) 260.32,1110.16 291.26,1079.21 U1.1@305.35,1079.21
  Signal Layer 2 w8: v2(260.32,1130.16) 260.32,1190.16 320.32,1250.16 320.32,1499.68 J2.2@270,1550
NetJ6_2: J6.2 U1.23 | length 489.6
  Top Layer w8: v2@330.16,1150 344.28,1135.87 344.28,1133.74 350.63,1127.39 U1.23@350.63,1104.8
  Signal Layer 2 w8: v2@333.16,1150 333.16,1180.55 360.32,1207.71 360.32,1490.32 J6.2@420,1550
  other v2: 333.16,1149.5
NetJ7_2: J7.2 U1.19 | length 509.3
  Top Layer w8: U1.19@429.37,1104.8 429.37,1126.76 436.03,1133.42 436.03,1135.87 440.16,1140 v2(450.16,1140)
  Signal Layer 2 w8: v2(450.16,1140) 498.35,1188.19 498.35,1478.35 J7.2@570,1550
NetL2_2: L2.2 R4.1 R10.2 | length 1317.4
  Top Layer w8: R10.2@657.72,1130 v1(690,1130)
  Signal Layer 3 w8: v1(690,1130) 690,1502.45 737.55,1550 1402.99,1550 1470,1482.99 1470,1439.39 v4(1440.61,1410)
NetQ1_4: Q1.4 Q2.4 R2.2 R3.1 | length 364.6
  Top Layer w16: R2.2@750,770 v1(750,797.28) ; R3.1@990,770 v1(990,797.28)
  Signal Layer 3 w16: v1(750,797.28) v1(990,797.28)
  Bottom Layer w16: Q2.4@715,797.28 v1(750,797.28) ; Q1.4@955,797.28 v1(990,797.28)
NetQ3_4: Q3.4 Q4.4 R7.2 R9.1 | length 424.4
  Top Layer w16: v1(1050,660) R9.1@1050,690 ; v1(1300,660) R7.2@1300,690
  Signal Layer 3 w16: v1(1050,660) 1080,690 1270,690 v1(1300,660)
  Bottom Layer w16: v1(1050,660) 1055,665 Q3.4@1055,702.72 ; v1(1300,660) 1305,665 Q4.4@1305,702.72
NetR2_1: R2.1 U1.13 | length 568
  Top Layer w9.5: U1.13@454.96,980.79 465.61,980.79 v2(496.39,950)
  Top Layer w10: v2(496.39,950) v2@500.16,950
  Top Layer w16: v1(750,680) R2.1@750,710
  Signal Layer 3 w16: v2(496.39,950) 496.39,755.25 571.65,680 625.52,680 625.83,679.69 638.99,679.69 639.3,680 v1(750,680) ; v2@500,949.84 v2@500.16,950
NetR3_2: R3.2 U1.14 | length 829.3
  Top Layer w9.5: U1.14@454.96,1000.47 479.69,1000.47 v2(500.16,980)
  Top Layer w16: R3.2@990,710 990,690 v1(1000,680)
  Signal Layer 3 w16: v2(500.16,980) 510,980 525.13,964.87 525.13,933.13 523.13,931.13 523.13,906.87 525.13,904.87 525.13,764.87 583.13,706.87 973.13,706.87 ; 974.13,705.87 v1(1000,680)
NetR5_2: R5.2 R14.1 U1.6 | length 217.7
  Top Layer w8: R5.2@207.56,830 R14.1@207.56,883.13 ; R14.1@207.72,890 240.16,890 270.16,920 270.16,970 280.94,980.79 U1.6@305.35,980.79
NetR6_2: R6.2 TP1.1 U1.21 | length 889
  Top Layer w8: U1.21@390,1104.8 v2@390,1149.84 ; TP1.1@490.02,1840 R6.2@592.44,1840
  Signal Layer 2 w8: v2(390.16,1150) 470.32,1230.16 470.32,1610.32 490.35,1630.35 TP1.1@490.02,1840 TP1.1@490,1850
NetR7_1: R7.1 U1.7 | length 1139.2
  Top Layer w9.5: v2(306.75,920) 330.94,944.2 U1.7@330.94,955.2
  Top Layer w16: v1(1260,750) 1270,750 R7.1@1300,750
  Signal Layer 2 w16: v2(306.75,920) 306.75,919.48 313.28,912.95 313.28,908.87 492.22,729.93 492.22,729.33 501.52,720.03 1007.36,720.03 1010.36,717.03 1033.63,717.03 1036.6,720 1230,720 v1(1260,750)
NetR9_2: R9.2 U1.8 | length 824.9
  Top Layer w9.5: v2(340.16,920) 350.63,930.47 U1.8@350.63,955.2
  Top Layer w16: v1(1022.5,743.9) 1028.6,750 R9.2@1050,750
  Signal Layer 2 w16: v2(340.16,920) 510,750 516.1,743.9 v1(1022.5,743.9)
NetR13_2: R13.2 U1.4 | length 87.5
  Top Layer w8: R13.2@217.87,1020.16 U1.4@305.35,1020.16
PGND: C2.2 C3.2 C4.2 C5.2 C6.2 C7.2 C8.2 C9.2 C10.2 C11.2 C13.1 C14.1 C17.2 C18.2 C19.2 C20.2 C21.2 C22.2 D2.2 J1.2 J5.1 NT1.2 Q3.1 Q3.2 Q3.3 Q4.1 Q4.2 Q4.3 R1.1 R8.1 U1.9 U1.25 | length 151.6
  Top Layer w10: C13.1@342.6,880 342.6,883.11 370.32,910.83 U1.9@370.32,955.2 U1.25@370.32,1020.16
  other v1: 1000,600 1050,600 1100,600 1150,600 1200,600 1250,600 1300,600 1350,600 1400,600 1450,600 1500,600 1550,600 1600,600 1000,630 1050,630 1100,630 1150,630 1200,630 1250,630 1300,630 1350,630 1400,630 1450,630 1500,630 1550,630 1600,630 1100,660 1150,660 1200,660 1250,660 1350,660 1400,660 1450,660 1500,660 1550,660 1600,660 1670,900 1720,900 1770,900 1820,900 1870,900 1920,900 1970,900 2020,900 2070,900 2120,900 2170,900 2220,900 2270,900 550,920 1670,950 1720,950 1770,950 1820,950 1870,950 1920,950 1970,950 2020,950 2070,950 2120,950 2170,950 2220,950 2270,950 610,960 1720,1000 1770,1000 1820,1000 1870,1000 1920,1000 1970,1000 2020,1000 2070,1000 2120,1000 2170,1000 2220,1000 2270,1000 1460,1320
  other v2: 300,850 300,880
  other v3: 380.16,986.69 336.85,1030 380.16,1030 423.46,1030 380.16,1073.31
VCC: C13.2 D1.2 U1.10 | length 185.3
  Top Layer w9.5: U1.10@390,955.2 390,887.72 C13.2@397.72,880
  Top Layer w12: D1.2@356.85,790 356.85,806.69 397.72,847.56 C13.2@397.72,880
